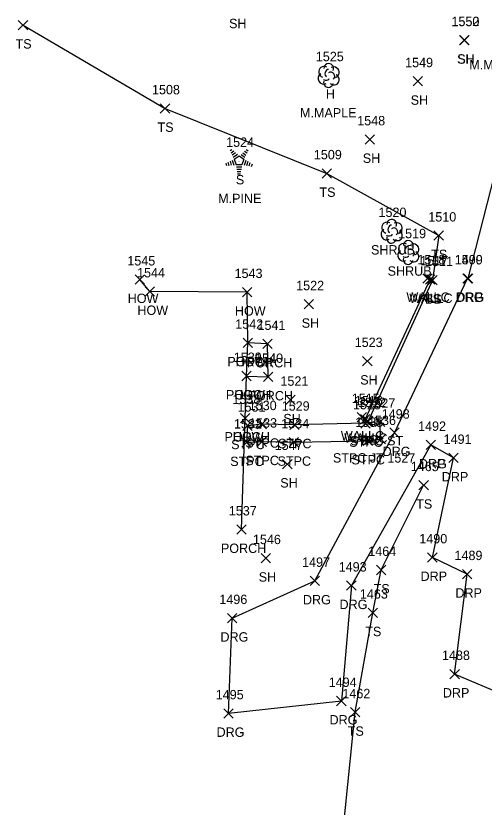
# Model space of a CAD drawing. Extents: x 462930 to 463548, y 29607 to 30453.
# Drawn here: x 463290.2 to 463320.6, y 30059.7 to 30111.1 of the extents above; entities that cross this region are included whole.
import ezdxf

# ---------------------------------------------------------------- set-up
doc = ezdxf.new("R2010")
doc.units = 0
for name, color, linetype in [('L_A', 7, 'Continuous'), ('L_C', 7, 'Continuous'), ('L_I', 7, 'Continuous'), ('L_TIC', 7, 'Continuous'), ('LBC', 7, 'Continuous'), ('LBF', 7, 'Continuous'), ('LELB', 7, 'Continuous'), ('LSH', 7, 'Continuous'), ('LTC', 7, 'Continuous'), ('LTD', 7, 'Continuous'), ('LW', 7, 'Continuous'), ('R_A', 7, 'Continuous'), ('R_I', 7, 'Continuous'), ('R_TIC', 7, 'Continuous'), ('RDG', 7, 'Continuous'), ('RDP', 7, 'Continuous')]:
    doc.layers.add(name, color=color, linetype=linetype)

msp = doc.modelspace()

# ---------------------------------------------------------------- linework, layer by layer
at = {"layer": 'L_TIC'}
for points in [[(463290.322, 30110.163), (463290.932, 30110.773)], [(463290.932, 30110.163), (463290.322, 30110.773)], [(463318.951, 30109.185), (463319.561, 30109.795)], [(463319.561, 30109.185), (463318.951, 30109.795)], [(463318.972, 30109.178), (463319.582, 30109.788)], [(463319.582, 30109.178), (463318.972, 30109.788)], [(463315.943, 30106.514), (463316.553, 30107.124)], [(463316.553, 30106.514), (463315.943, 30107.124)], [(463299.536, 30104.753), (463300.146, 30105.363)], [(463300.146, 30104.753), (463299.536, 30105.363)], [(463312.832, 30102.738), (463313.442, 30103.348)], [(463313.442, 30102.738), (463312.832, 30103.348)], [(463310.044, 30100.532), (463310.654, 30101.142)], [(463310.654, 30100.532), (463310.044, 30101.142)], [(463317.298, 30096.49), (463317.908, 30097.1)], [(463317.908, 30096.49), (463317.298, 30097.1)], [(463297.91, 30093.636), (463298.52, 30094.246)], [(463298.52, 30093.636), (463297.91, 30094.246)], [(463316.564, 30093.712), (463317.174, 30094.322)], [(463317.174, 30093.712), (463316.564, 30094.322)], [(463316.748, 30093.644), (463317.358, 30094.254)], [(463317.358, 30093.644), (463316.748, 30094.254)], [(463316.892, 30093.594), (463317.502, 30094.204)], [(463317.502, 30093.594), (463316.892, 30094.204)], [(463316.892, 30093.594), (463317.502, 30094.204)], [(463317.502, 30093.594), (463316.892, 30094.204)], [(463298.544, 30092.863), (463299.154, 30093.473)], [(463299.154, 30092.863), (463298.544, 30093.473)], [(463304.872, 30092.821), (463305.482, 30093.431)], [(463305.482, 30092.821), (463304.872, 30093.431)], [(463308.869, 30092.031), (463309.479, 30092.641)], [(463309.479, 30092.031), (463308.869, 30092.641)], [(463304.914, 30089.527), (463305.524, 30090.137)], [(463305.524, 30089.527), (463304.914, 30090.137)], [(463304.914, 30089.527), (463305.524, 30090.137)], [(463305.524, 30089.527), (463304.914, 30090.137)], [(463306.187, 30089.453), (463306.797, 30090.063)], [(463306.797, 30089.453), (463306.187, 30090.063)], [(463312.668, 30088.34), (463313.278, 30088.95)], [(463313.278, 30088.34), (463312.668, 30088.95)], [(463304.824, 30087.371), (463305.434, 30087.981)], [(463305.434, 30087.371), (463304.824, 30087.981)], [(463304.824, 30087.371), (463305.434, 30087.981)], [(463305.434, 30087.371), (463304.824, 30087.981)], [(463306.232, 30087.311), (463306.842, 30087.921)], [(463306.842, 30087.311), (463306.232, 30087.921)], [(463307.677, 30085.824), (463308.287, 30086.434)], [(463308.287, 30085.824), (463307.677, 30086.434)], [(463304.733, 30084.642), (463305.343, 30085.252)], [(463305.343, 30084.642), (463304.733, 30085.252)], [(463304.733, 30084.642), (463305.343, 30085.252)], [(463305.343, 30084.642), (463304.733, 30085.252)], [(463312.309, 30084.704), (463312.919, 30085.314)], [(463312.919, 30084.704), (463312.309, 30085.314)], [(463312.525, 30084.557), (463313.135, 30085.167)], [(463313.135, 30084.557), (463312.525, 30085.167)], [(463304.892, 30084.146), (463305.502, 30084.756)], [(463305.502, 30084.146), (463304.892, 30084.756)], [(463305.817, 30084.241), (463306.427, 30084.851)], [(463306.427, 30084.241), (463305.817, 30084.851)], [(463307.933, 30084.206), (463308.543, 30084.816)], [(463308.543, 30084.206), (463307.933, 30084.816)], [(463312.555, 30084.298), (463313.165, 30084.908)], [(463313.165, 30084.298), (463312.555, 30084.908)], [(463312.716, 30084.44), (463313.326, 30085.05)], [(463313.326, 30084.44), (463312.716, 30085.05)], [(463313.488, 30084.393), (463314.098, 30085.003)], [(463314.098, 30084.393), (463313.488, 30085.003)], [(463304.83, 30083.048), (463305.44, 30083.658)], [(463305.44, 30083.048), (463304.83, 30083.658)], [(463305.815, 30083.107), (463306.425, 30083.717)], [(463306.425, 30083.107), (463305.815, 30083.717)], [(463307.903, 30083.066), (463308.513, 30083.676)], [(463308.513, 30083.066), (463307.903, 30083.676)], [(463312.703, 30083.154), (463313.313, 30083.764)], [(463313.313, 30083.154), (463312.703, 30083.764)], [(463313.549, 30083.273), (463314.159, 30083.883)], [(463314.159, 30083.273), (463313.549, 30083.883)], [(463307.477, 30081.653), (463308.087, 30082.263)], [(463308.087, 30081.653), (463307.477, 30082.263)], [(463316.322, 30080.278), (463316.932, 30080.888)], [(463316.932, 30080.278), (463316.322, 30080.888)], [(463304.499, 30077.401), (463305.109, 30078.011)], [(463305.109, 30077.401), (463304.499, 30078.011)], [(463306.08, 30075.539), (463306.69, 30076.149)], [(463306.69, 30075.539), (463306.08, 30076.149)], [(463313.561, 30074.772), (463314.171, 30075.382)], [(463314.171, 30074.772), (463313.561, 30075.382)], [(463313.019, 30071.998), (463313.629, 30072.608)], [(463313.629, 30071.998), (463313.019, 30072.608)], [(463311.882, 30065.529), (463312.492, 30066.139)], [(463312.492, 30065.529), (463311.882, 30066.139)]]:
    msp.add_lwpolyline(points, dxfattribs=at)
at = {"layer": 'LBC'}
msp.add_lwpolyline([(463305.038, 30084.947), (463305.129, 30087.676), (463305.219, 30089.832), (463305.177, 30093.126), (463298.849, 30093.168), (463298.215, 30093.941)], dxfattribs=at)
at = {"layer": 'LBF'}
for points in [[(463305.129, 30087.676), (463306.537, 30087.616), (463306.492, 30089.758), (463305.219, 30089.832)], [(463304.804, 30077.706), (463305.038, 30084.947)], [(463313.793, 30084.698), (463312.86, 30084.603), (463308.238, 30084.511), (463306.122, 30084.546), (463305.197, 30084.451), (463305.135, 30083.353), (463306.12, 30083.412), (463308.208, 30083.371), (463313.008, 30083.459), (463313.854, 30083.578)], [(463313.854, 30083.578), (463313.793, 30084.698)]]:
    msp.add_lwpolyline(points, dxfattribs=at)
at = {"layer": 'LELB'}
for points in [[(463290.627, 30110.468), (463299.841, 30105.058), (463310.349, 30100.837), (463317.603, 30096.795), (463317.197, 30093.899)], [(463317.197, 30093.899), (463313.021, 30084.745)], [(463310.927, 30053.464), (463312.187, 30065.834), (463313.324, 30072.303), (463313.866, 30075.077), (463316.627, 30080.583)]]:
    msp.add_lwpolyline(points, dxfattribs=at)
at = {"layer": 'LSH'}
for p, q in [((463314.544, 30097.091), (463314.544, 30097.091)), ((463314.544, 30097.091), (463314.544, 30097.091)), ((463315.622, 30095.714), (463315.622, 30095.714)), ((463315.622, 30095.714), (463315.622, 30095.714))]:
    msp.add_line(p, q, dxfattribs=at)
for centre in [(463314.558, 30097.528), (463315.636, 30096.151)]:
    msp.add_arc(centre, 0.319, 335.5272, 180.9563, dxfattribs=at)
for centre, major_axis, ratio, start_param, end_param in [((463314.303, 30097.294), (0.369, -0.156), 0.895232, 1.570796, 4.712389), ((463314.48, 30097.231), (-0.063, -0.241), 0.645439, 3.141593, 6.283185), ((463314.861, 30097.269), (-0.348, -0.147), 0.949671, 1.570796, 4.712389), ((463314.214, 30096.875), (0.178, -0.317), 0.959034, 3.141593, 6.283185), ((463314.696, 30097.04), (-0.152, 0.203), 0.989748, 3.141593, 6.283185), ((463314.849, 30096.837), (-0.332, 0.241), 0.841452, 1.570796, 4.712389), ((463314.544, 30096.634), (0.081, 0.323), 0.942809, 1.570796, 4.712389), ((463314.404, 30096.862), (-0.19, -0.025), 0.423636, 0, 3.141593), ((463315.381, 30095.917), (0.369, -0.156), 0.895232, 1.570796, 4.712389), ((463315.558, 30095.854), (-0.063, -0.241), 0.645439, 3.141593, 6.283185), ((463315.774, 30095.663), (-0.152, 0.203), 0.989748, 3.141593, 6.283185), ((463315.939, 30095.892), (-0.348, -0.147), 0.949671, 1.570796, 4.712389), ((463315.292, 30095.498), (0.178, -0.317), 0.959034, 3.141593, 6.283185), ((463315.482, 30095.485), (-0.19, -0.025), 0.423636, 0, 3.141593), ((463315.927, 30095.46), (-0.332, 0.241), 0.841452, 1.570796, 4.712389), ((463315.622, 30095.257), (0.081, 0.323), 0.942809, 1.570796, 4.712389)]:
    msp.add_ellipse(centre, major_axis=major_axis, ratio=ratio, start_param=start_param, end_param=end_param, dxfattribs=at)
at = {"layer": 'LTC'}
for p, q in [((463304.079, 30102.319), (463304.187, 30102.398)), ((463304.143, 30102.177), (463304.304, 30102.294)), ((463304.207, 30102.035), (463304.421, 30102.191)), ((463304.271, 30101.893), (463304.538, 30102.088)), ((463304.775, 30102.074), (463305.022, 30101.894)), ((463304.889, 30102.18), (463305.096, 30102.029)), ((463305.002, 30102.286), (463305.169, 30102.164)), ((463305.115, 30102.392), (463305.242, 30102.299)), ((463303.923, 30101.556), (463303.987, 30101.357)), ((463304.062, 30101.622), (463304.144, 30101.367)), ((463304.2, 30101.688), (463304.301, 30101.377)), ((463304.339, 30101.755), (463304.647, 30101.978)), ((463304.339, 30101.755), (463304.457, 30101.391)), ((463304.647, 30101.978), (463304.951, 30101.757)), ((463304.951, 30101.757), (463304.832, 30101.391)), ((463305.085, 30101.675), (463304.982, 30101.358)), ((463305.22, 30101.599), (463305.132, 30101.329)), ((463303.784, 30101.49), (463303.83, 30101.347)), ((463304.832, 30101.391), (463304.457, 30101.391)), ((463304.82, 30101.238), (463304.471, 30101.238)), ((463304.795, 30101.086), (463304.494, 30101.086)), ((463305.356, 30101.522), (463305.283, 30101.3)), ((463305.491, 30101.446), (463305.434, 30101.271)), ((463304.769, 30100.934), (463304.516, 30100.934)), ((463304.744, 30100.781), (463304.538, 30100.781))]:
    msp.add_line(p, q, dxfattribs=at)
at = {"layer": 'LTD'}
msp.add_line((463310.452, 30107.21), (463310.452, 30107.21), dxfattribs=at)
msp.add_line((463310.452, 30107.21), (463310.452, 30107.21), dxfattribs=at)
msp.add_arc((463310.466, 30107.647), 0.319, 335.5272, 180.9563, dxfattribs=at)
for centre, major_axis, ratio, start_param, end_param in [((463310.211, 30107.413), (0.369, -0.156), 0.895232, 1.570796, 4.712389), ((463310.769, 30107.388), (-0.348, -0.147), 0.949671, 1.570796, 4.712389), ((463310.122, 30106.994), (0.178, -0.317), 0.959034, 3.141593, 6.283185), ((463310.388, 30107.35), (-0.063, -0.241), 0.645439, 3.141593, 6.283185), ((463310.604, 30107.159), (-0.152, 0.203), 0.989748, 3.141593, 6.283185), ((463310.757, 30106.956), (-0.332, 0.241), 0.841452, 1.570796, 4.712389), ((463310.452, 30106.753), (0.081, 0.323), 0.942809, 1.570796, 4.712389), ((463310.312, 30106.981), (-0.19, -0.025), 0.423636, 0, 3.141593)]:
    msp.add_ellipse(centre, major_axis=major_axis, ratio=ratio, start_param=start_param, end_param=end_param, dxfattribs=at)
at = {"layer": 'LW'}
msp.add_lwpolyline([(463312.614, 30085.009), (463312.83, 30084.862), (463317.053, 30093.949), (463316.869, 30094.017)], dxfattribs=at)
at = {"layer": 'R_TIC'}
for points in [[(463319.167, 30093.703), (463319.777, 30094.313)], [(463319.777, 30093.703), (463319.167, 30094.313)], [(463319.208, 30093.713), (463319.818, 30094.323)], [(463319.818, 30093.713), (463319.208, 30094.323)], [(463319.208, 30093.713), (463319.818, 30094.323)], [(463319.818, 30093.713), (463319.208, 30094.323)], [(463314.423, 30083.691), (463315.033, 30084.301)], [(463315.033, 30083.691), (463314.423, 30084.301)], [(463316.782, 30082.895), (463317.392, 30083.505)], [(463317.392, 30082.895), (463316.782, 30083.505)], [(463316.782, 30082.895), (463317.392, 30083.505)], [(463317.392, 30082.895), (463316.782, 30083.505)], [(463318.265, 30082.049), (463318.875, 30082.659)], [(463318.875, 30082.049), (463318.265, 30082.659)], [(463316.886, 30075.588), (463317.496, 30076.198)], [(463317.496, 30075.588), (463316.886, 30076.198)], [(463319.147, 30074.502), (463319.757, 30075.112)], [(463319.757, 30074.502), (463319.147, 30075.112)], [(463309.254, 30074.062), (463309.864, 30074.672)], [(463309.864, 30074.062), (463309.254, 30074.672)], [(463311.629, 30073.757), (463312.239, 30074.367)], [(463312.239, 30073.757), (463311.629, 30074.367)], [(463303.9, 30071.644), (463304.51, 30072.254)], [(463304.51, 30071.644), (463303.9, 30072.254)], [(463318.333, 30068.014), (463318.943, 30068.624)], [(463318.943, 30068.014), (463318.333, 30068.624)], [(463310.98, 30066.262), (463311.59, 30066.872)], [(463311.59, 30066.262), (463310.98, 30066.872)], [(463303.649, 30065.459), (463304.259, 30066.069)], [(463304.259, 30065.459), (463303.649, 30066.069)]]:
    msp.add_lwpolyline(points, dxfattribs=at)
at = {"layer": 'RDG'}
msp.add_lwpolyline([(463317.087, 30083.2), (463311.934, 30074.062), (463311.285, 30066.567), (463303.954, 30065.764), (463304.205, 30071.949), (463309.559, 30074.367), (463314.728, 30083.996), (463319.472, 30094.008), (463319.513, 30094.018)], dxfattribs=at)
at = {"layer": 'RDP'}
for points in [[(463319.513, 30094.018), (463322.216, 30104.589), (463322.678, 30111.184), (463317.965, 30116.023), (463310.345, 30118.227), (463299.708, 30118.434), (463291.709, 30117.924)], [(463329.61, 30107.203), (463326.001, 30103.02), (463321.75, 30087.148), (463322.748, 30078.455), (463323.504, 30066.246), (463318.638, 30068.319), (463319.452, 30074.807), (463317.191, 30075.893), (463318.57, 30082.354), (463317.087, 30083.2)]]:
    msp.add_lwpolyline(points, dxfattribs=at)

# ---------------------------------------------------------------- texts
at = {"layer": 'L_A'}
for s, height, p in [('SH', 0.6096, (463303.999, 30110.267)), ('TS', 0.6096, (463290.142, 30108.944)), ('SH', 0.6096, (463318.795, 30107.966)), ('SH', 0.6096, (463318.816, 30107.959)), ('H', 0.61, (463310.279, 30105.686)), ('SH', 0.6096, (463315.787, 30105.295)), ('TS', 0.6096, (463299.356, 30103.534)), ('SH', 0.6096, (463312.676, 30101.519)), ('S', 0.61, (463304.442, 30100.122)), ('TS', 0.6096, (463309.864, 30099.313)), ('SHRUB', 0.6096, (463313.212, 30095.567)), ('TS', 0.6096, (463317.118, 30095.271)), ('SHRUB', 0.6096, (463314.29, 30094.19)), ('HOW', 0.6096, (463297.418, 30092.417)), ('WALLC', 0.6096, (463315.508, 30092.493)), ('WALLC', 0.6096, (463315.692, 30092.425)), ('TS', 0.6096, (463316.712, 30092.375)), ('BS', 0.6096, (463316.722, 30092.375)), ('HOW', 0.6096, (463298.052, 30091.644)), ('HOW', 0.6096, (463304.38, 30091.602)), ('SH', 0.6096, (463308.713, 30090.812)), ('PORCH', 0.6096, (463303.885, 30088.308)), ('HOW', 0.6096, (463304.422, 30088.308)), ('PORCH', 0.6096, (463305.158, 30088.234)), ('SH', 0.6096, (463312.512, 30087.121)), ('PORCH', 0.6096, (463303.795, 30086.152)), ('HOW', 0.6096, (463304.332, 30086.152)), ('PORCH', 0.6096, (463305.203, 30086.092)), ('SH', 0.6096, (463307.521, 30084.605)), ('WALLC', 0.6096, (463311.253, 30083.485)), ('PORCH', 0.6096, (463303.704, 30083.423)), ('HOW', 0.6096, (463304.241, 30083.423)), ('STPC', 0.6096, (463305.059, 30083.022)), ('STPC', 0.6096, (463307.175, 30082.987)), ('WALLC', 0.6096, (463311.469, 30083.338)), ('STPC', 0.6096, (463311.797, 30083.079)), ('STPC ST', 0.6096, (463311.856, 30083.174)), ('BS', 0.6096, (463312.546, 30083.221)), ('STPC', 0.6096, (463304.134, 30082.927)), ('STPC JT 1527', 0.6096, (463310.739, 30082.054)), ('STPC', 0.6096, (463311.945, 30081.935)), ('STPC', 0.6096, (463304.072, 30081.829)), ('STPC', 0.6096, (463305.057, 30081.888)), ('STPC', 0.6096, (463307.145, 30081.847)), ('SH', 0.6096, (463307.321, 30080.434)), ('TS', 0.6096, (463316.142, 30079.059)), ('PORCH', 0.6096, (463303.47, 30076.182)), ('SH', 0.6096, (463305.924, 30074.32)), ('TS', 0.6096, (463313.381, 30073.553)), ('TS', 0.6096, (463312.839, 30070.779)), ('TS', 0.6096, (463311.702, 30064.31))]:
    msp.add_text(s, height=height, dxfattribs=at).set_placement(p)
at = {"layer": 'L_C'}
for s, p in [('M.MAPLE', (463319.586, 30107.59)), ('M.MAPLE', (463308.604, 30104.467)), ('M.PINE', (463303.29, 30098.903))]:
    msp.add_text(s, height=0.6096, dxfattribs=at).set_placement(p)
at = {"layer": 'L_I'}
for s, p in [('1550', (463318.43, 30110.397)), ('1552', (463318.435, 30110.404)), ('1525', (463309.631, 30108.124)), ('1549', (463315.425, 30107.733)), ('1508', (463298.996, 30105.972)), ('1548', (463312.316, 30103.957)), ('1524', (463303.808, 30102.56)), ('1509', (463309.502, 30101.751)), ('1520', (463313.697, 30098.005)), ('1510', (463316.929, 30097.709)), ('1519', (463314.972, 30096.628)), ('1545', (463297.394, 30094.855)), ('1518', (463316.221, 30094.931)), ('1517', (463316.405, 30094.863)), ('1511', (463316.722, 30094.813)), ('1511', (463316.722, 30094.813)), ('1544', (463298.028, 30094.082)), ('1543', (463304.356, 30094.04)), ('1522', (463308.353, 30093.25)), ('1542', (463304.398, 30090.746)), ('1542', (463304.398, 30090.746)), ('1541', (463305.844, 30090.672)), ('1523', (463312.152, 30089.559)), ('1539', (463304.306, 30088.59)), ('1539', (463304.306, 30088.59)), ('1540', (463305.69, 30088.53)), ('1521', (463307.334, 30087.043)), ('1538', (463304.217, 30085.861)), ('1538', (463304.217, 30085.861)), ('1515', (463311.966, 30085.923)), ('1528', (463312.039, 30085.517)), ('1516', (463312.165, 30085.776)), ('1512', (463312.373, 30085.659)), ('1527', (463312.972, 30085.612)), ('1531', (463304.549, 30085.365)), ('1530', (463305.275, 30085.46)), ('1529', (463307.415, 30085.425)), ('1536', (463313.016, 30084.492)), ('1532', (463304.314, 30084.267)), ('1533', (463305.299, 30084.326)), ('1534', (463307.387, 30084.285)), ('1535', (463312.187, 30084.373)), ('1547', (463306.961, 30082.872)), ('1465', (463315.792, 30081.497)), ('1537', (463303.983, 30078.62)), ('1546', (463305.547, 30076.758)), ('1464', (463313.031, 30075.991)), ('1463', (463312.489, 30073.217)), ('1462', (463311.352, 30066.748))]:
    msp.add_text(s, height=0.6096, dxfattribs=at).set_placement(p)
at = {"layer": 'LTC'}
msp.add_text('.', height=0.316, rotation=270, dxfattribs=at).set_placement((463304.612, 30101.678))
at = {"layer": 'R_A'}
for s, p in [('DRG', (463318.706, 30092.484)), ('DRG', (463318.747, 30092.494)), ('DRP', (463318.747, 30092.494)), ('DRG', (463313.962, 30082.472)), ('DRG', (463316.321, 30081.676)), ('DRP', (463316.321, 30081.676)), ('DRP', (463317.804, 30080.83)), ('DRP', (463316.425, 30074.369)), ('DRP', (463318.686, 30073.283)), ('DRG', (463308.793, 30072.843)), ('DRG', (463311.168, 30072.538)), ('DRG', (463303.439, 30070.425)), ('DRP', (463317.872, 30066.795)), ('DRG', (463310.519, 30065.043)), ('DRG', (463303.188, 30064.24))]:
    msp.add_text(s, height=0.6096, dxfattribs=at).set_placement(p)
at = {"layer": 'R_I'}
for s, p in [('1500', (463318.642, 30094.932)), ('1500', (463318.642, 30094.932)), ('1499', (463318.649, 30094.922)), ('1498', (463313.907, 30084.91)), ('1492', (463316.266, 30084.114)), ('1492', (463316.266, 30084.114)), ('1491', (463317.922, 30083.268)), ('1490', (463316.344, 30076.807)), ('1497', (463308.738, 30075.281)), ('1489', (463318.629, 30075.721)), ('1493', (463311.113, 30074.976)), ('1496', (463303.367, 30072.863)), ('1488', (463317.817, 30069.233)), ('1494', (463310.464, 30067.481)), ('1495', (463303.133, 30066.678))]:
    msp.add_text(s, height=0.6096, dxfattribs=at).set_placement(p)

doc.saveas('drawing.dxf')
